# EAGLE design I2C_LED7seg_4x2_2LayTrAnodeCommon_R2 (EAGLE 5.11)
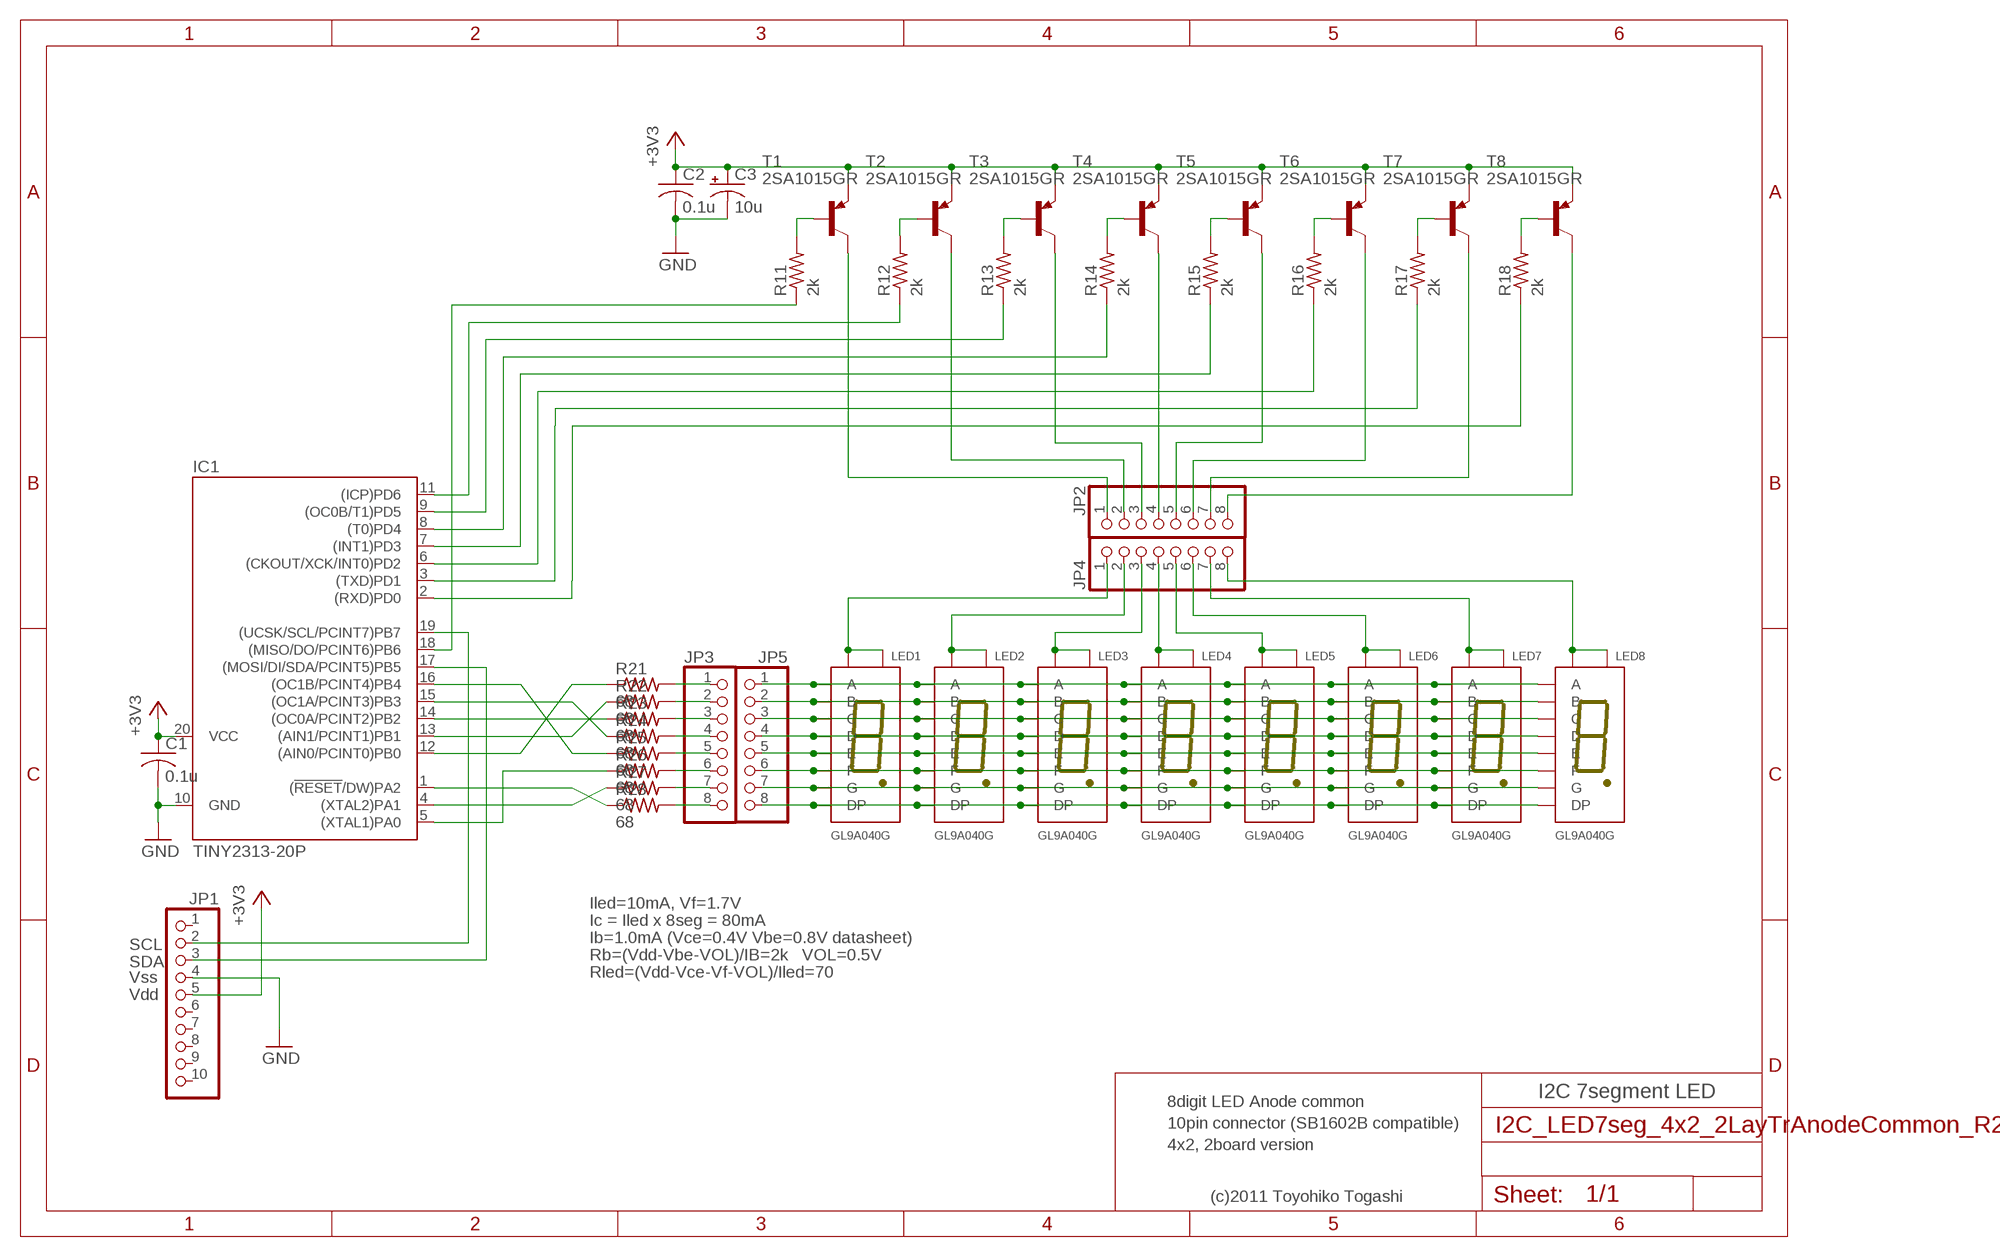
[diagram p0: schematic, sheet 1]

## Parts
C1  0.1u  C-US025-024X044  [C025-024X044]
C2  0.1u  C-US025-024X044  [C025-024X044]
C3  10u  CPOL-USE2.5-6  [E2,5-6]
IC1  TINY2313-20P  [DIL20]
JP1  PINHD-1X10  [1X10]
JP2  PINHD-1X8  [1X08]
JP3  PINHD-1X8  [1X08]
JP4  PINHD-1X8  [1X08]
JP5  PINHD-1X8  [1X08]
LED1  GL9A040G  [GL9A040G]
LED2  GL9A040G  [GL9A040G]
LED3  GL9A040G  [GL9A040G]
LED4  GL9A040G  [GL9A040G]
LED5  GL9A040G  [GL9A040G]
LED6  GL9A040G  [GL9A040G]
LED7  GL9A040G  [GL9A040G]
LED8  GL9A040G  [GL9A040G]
R11  2k  R-US_0207/10  [0207/10]
R12  2k  R-US_0204/2V  [0204V]
R13  2k  R-US_0204/2V  [0204V]
R14  2k  R-US_0204/2V  [0204V]
R15  2k  R-US_0204/7  [0204/7]
R16  2k  R-US_0204/7  [0204/7]
R17  2k  R-US_0204/2V  [0204V]
R18  2k  R-US_0204/5  [0204/5]
R21  68  R-US_0204/2V  [0204V]
R22  68  R-US_0204/2V  [0204V]
R23  68  R-US_0204/2V  [0204V]
R24  68  R-US_0204/2V  [0204V]
R25  68  R-US_0204/2V  [0204V]
R26  68  R-US_0204/2V  [0204V]
R27  68  R-US_0204/2V  [0204V]
R28  68  R-US_0204/2V  [0204V]
T1  2SA1015GR  2SC1815-PNP-TO92-BCE  [TO92-BCE]
T2  2SA1015GR  2SC1815-PNP-TO92-BCE  [TO92-BCE]
T3  2SA1015GR  2SC1815-PNP-TO92-BCE  [TO92-BCE]
T4  2SA1015GR  2SC1815-PNP-TO92-BCE  [TO92-BCE]
T5  2SA1015GR  2SC1815-PNP-TO92-BCE  [TO92-BCE]
T6  2SA1015GR  2SC1815-PNP-TO92-BCE  [TO92-BCE]
T7  2SA1015GR  2SC1815-PNP-TO92-BCE  [TO92-BCE]
T8  2SA1015GR  2SC1815-PNP-TO92-BCE  [TO92-BCE]

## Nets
+3V3: C1.1 C2.1 C3.+ IC1.20(VCC) JP1.5 T1.E T2.E T3.E T4.E T5.E T6.E T7.E T8.E
GND: C1.2 C2.2 C3.- IC1.10(GND) JP1.4
N$1: JP3.7 R27.2
N$2: JP3.8 R28.2
N$3: IC1.19((UCSK/SCL/PCINT7)PB7) JP1.2
N$4: IC1.17((MOSI/DI/SDA/PCINT5)PB5) JP1.3
N$5: JP3.1 R21.2
N$6: JP3.2 R22.2
N$7: JP3.3 R23.2
N$8: JP3.4 R24.2
N$9: JP3.5 R25.2
N$10: JP3.6 R26.2
N$11: JP2.8 T8.C
N$12: JP2.7 T7.C
N$13: R11.2 T1.B
N$14: IC1.5((XTAL1)PA0) R26.1
N$15: IC1.4((XTAL2)PA1) R27.1
N$16: IC1.1((!RESET!/DW)PA2) R28.1
N$17: IC1.12((AIN0/PCINT0)PB0) R21.1
N$18: JP4.1 LED1.P$1(CA1) LED1.P$6(CA6)
N$19: IC1.13((AIN1/PCINT1)PB1) R22.1
N$20: IC1.14((OC0A/PCINT2)PB2) R23.1
N$21: IC1.15((OC1A/PCINT3)PB3) R24.1
N$22: IC1.16((OC1B/PCINT4)PB4) R25.1
N$23: JP4.2 LED2.P$1(CA1) LED2.P$6(CA6)
N$24: JP4.3 LED3.P$1(CA1) LED3.P$6(CA6)
N$25: IC1.18((MISO/DO/PCINT6)PB6) R11.1
N$26: R18.2 T8.B
N$27: JP4.4 LED4.P$1(CA1) LED4.P$6(CA6)
N$28: IC1.2((RXD)PD0) R18.1
N$29: JP4.5 LED5.P$1(CA1) LED5.P$6(CA6)
N$30: JP4.6 LED6.P$1(CA1) LED6.P$6(CA6)
N$31: JP4.7 LED7.P$1(CA1) LED7.P$6(CA6)
N$32: JP4.8 LED8.P$1(CA1) LED8.P$6(CA6)
N$33: JP2.6 T6.C
N$34: JP2.5 T5.C
N$35: R12.2 T2.B
N$36: JP2.4 T4.C
N$37: JP2.3 T3.C
N$38: JP2.2 T2.C
N$39: JP2.1 T1.C
N$40: JP5.1 LED1.P$10(A) LED2.P$10(A) LED3.P$10(A) LED4.P$10(A) LED5.P$10(A) LED6.P$10(A) LED7.P$10(A) LED8.P$10(A)
N$41: JP5.2 LED1.P$9(B) LED2.P$9(B) LED3.P$9(B) LED4.P$9(B) LED5.P$9(B) LED6.P$9(B) LED7.P$9(B) LED8.P$9(B)
N$42: JP5.3 LED1.P$8(C) LED2.P$8(C) LED3.P$8(C) LED4.P$8(C) LED5.P$8(C) LED6.P$8(C) LED7.P$8(C) LED8.P$8(C)
N$43: JP5.4 LED1.P$5(D) LED2.P$5(D) LED3.P$5(D) LED4.P$5(D) LED5.P$5(D) LED6.P$5(D) LED7.P$5(D) LED8.P$5(D)
N$44: JP5.5 LED1.P$4(E) LED2.P$4(E) LED3.P$4(E) LED4.P$4(E) LED5.P$4(E) LED6.P$4(E) LED7.P$4(E) LED8.P$4(E)
N$45: JP5.6 LED1.P$2(F) LED2.P$2(F) LED3.P$2(F) LED4.P$2(F) LED5.P$2(F) LED6.P$2(F) LED7.P$2(F) LED8.P$2(F)
N$46: JP5.7 LED1.P$3(G) LED2.P$3(G) LED3.P$3(G) LED4.P$3(G) LED5.P$3(G) LED6.P$3(G) LED7.P$3(G) LED8.P$3(G)
N$47: JP5.8 LED1.P$7(DP) LED2.P$7(DP) LED3.P$7(DP) LED4.P$7(DP) LED5.P$7(DP) LED6.P$7(DP) LED7.P$7(DP) LED8.P$7(DP)
N$48: R13.2 T3.B
N$50: IC1.3((TXD)PD1) R17.1
N$53: IC1.7((INT1)PD3) R15.1
N$54: IC1.9((OC0B/T1)PD5) R13.1
N$60: R14.2 T4.B
N$72: R15.2 T5.B
N$84: R16.2 T6.B
N$96: R17.2 T7.B
N$98: IC1.11((ICP)PD6) R12.1
N$100: IC1.8((T0)PD4) R14.1
N$102: IC1.6((CKOUT/XCK/INT0)PD2) R16.1
Unconnected: JP1.1 JP1.6 JP1.7 JP1.8 JP1.9 JP1.10

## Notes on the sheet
- Iled=10mA, Vf=1.7V
- Ic = Iled x 8seg = 80mA
- Ib=1.0mA (Vce=0.4V Vbe=0.8V datasheet)
- SCL
- Rb=(Vdd-Vbe-VOL)/IB=2k   VOL=0.5V
- SDA
- Rled=(Vdd-Vce-Vf-VOL)/Iled=70
- Vss
- Vdd
- I2C 7segment LED
- 8digit LED Anode common
- 10pin connector (SB1602B compatible)
- 4x2, 2board version
- (c)2011 Toyohiko Togashi

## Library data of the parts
C1 C2 = rcl:C-US: CAPACITOR, American symbol
C3 = rcl:CPOL-US: POLARIZED CAPACITOR, American symbol
IC1 = TOG:TINY2313: 8-bit AVR Microcontroller with 2K Bytes Flash Source: http://www.atmel.com .. doc2543.pdf
JP1 = pinhead:PINHD-1X10: PIN HEADER
JP2-JP5 = pinhead:PINHD-1X8: PIN HEADER
LED1-LED8 = TOG:GL9A040G: 7 Segment LED
R11-R18 R21-R28 = rcl:R-US_: RESISTOR, American symbol
T1-T8 = transistor:*-PNP-: PNP Transistror

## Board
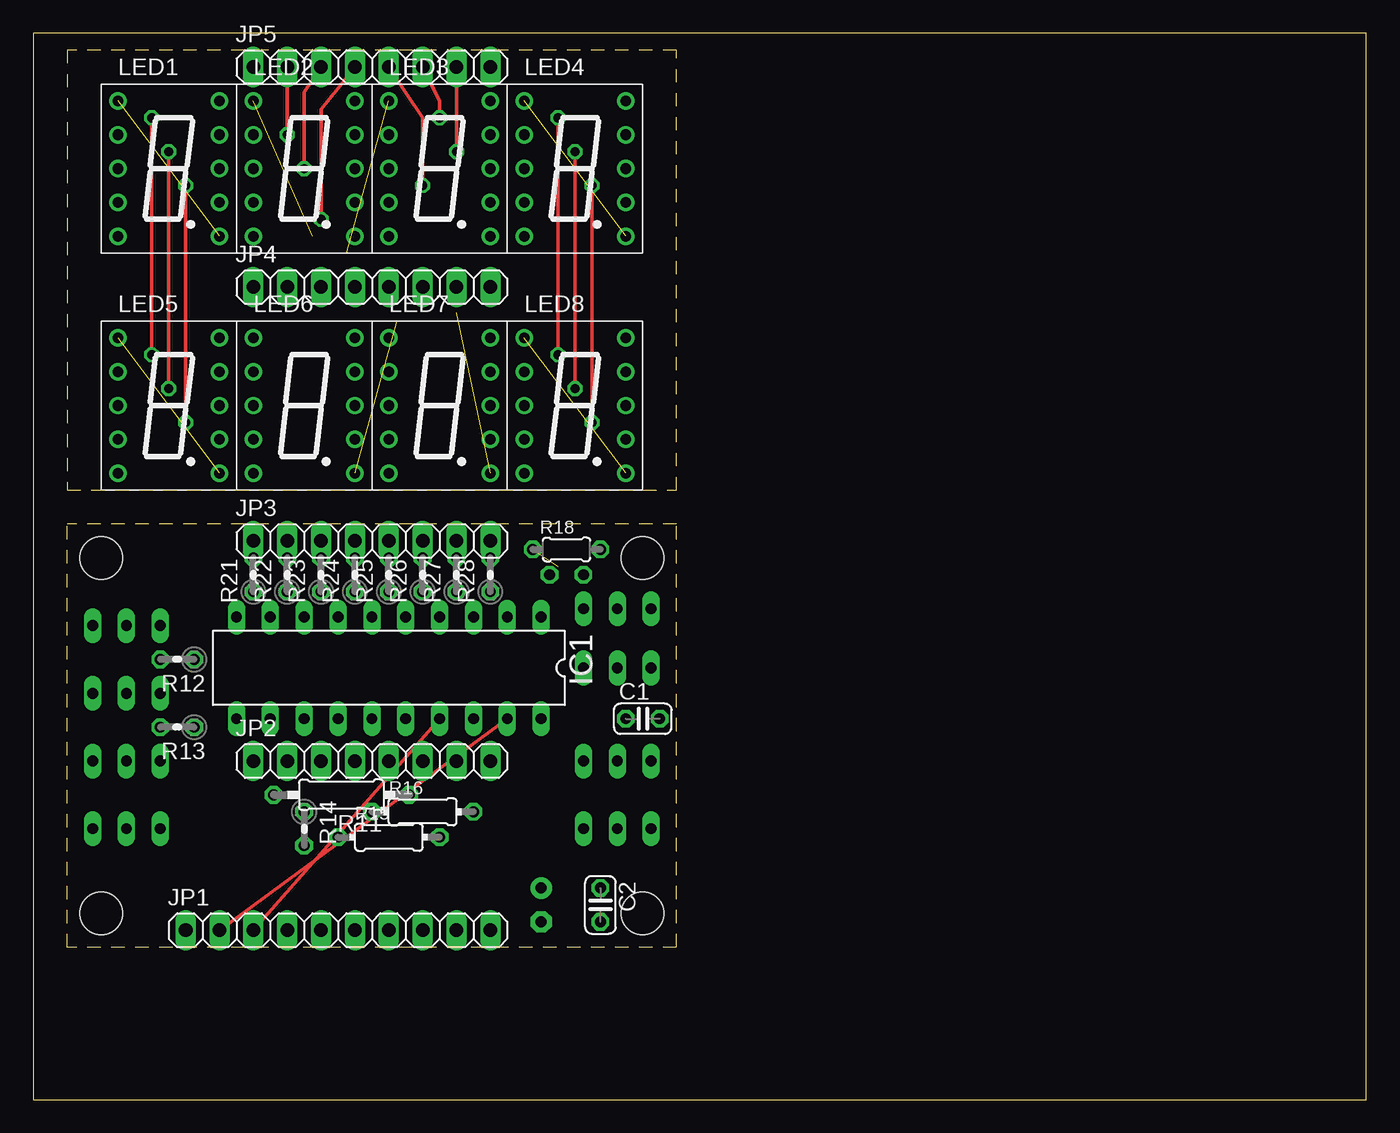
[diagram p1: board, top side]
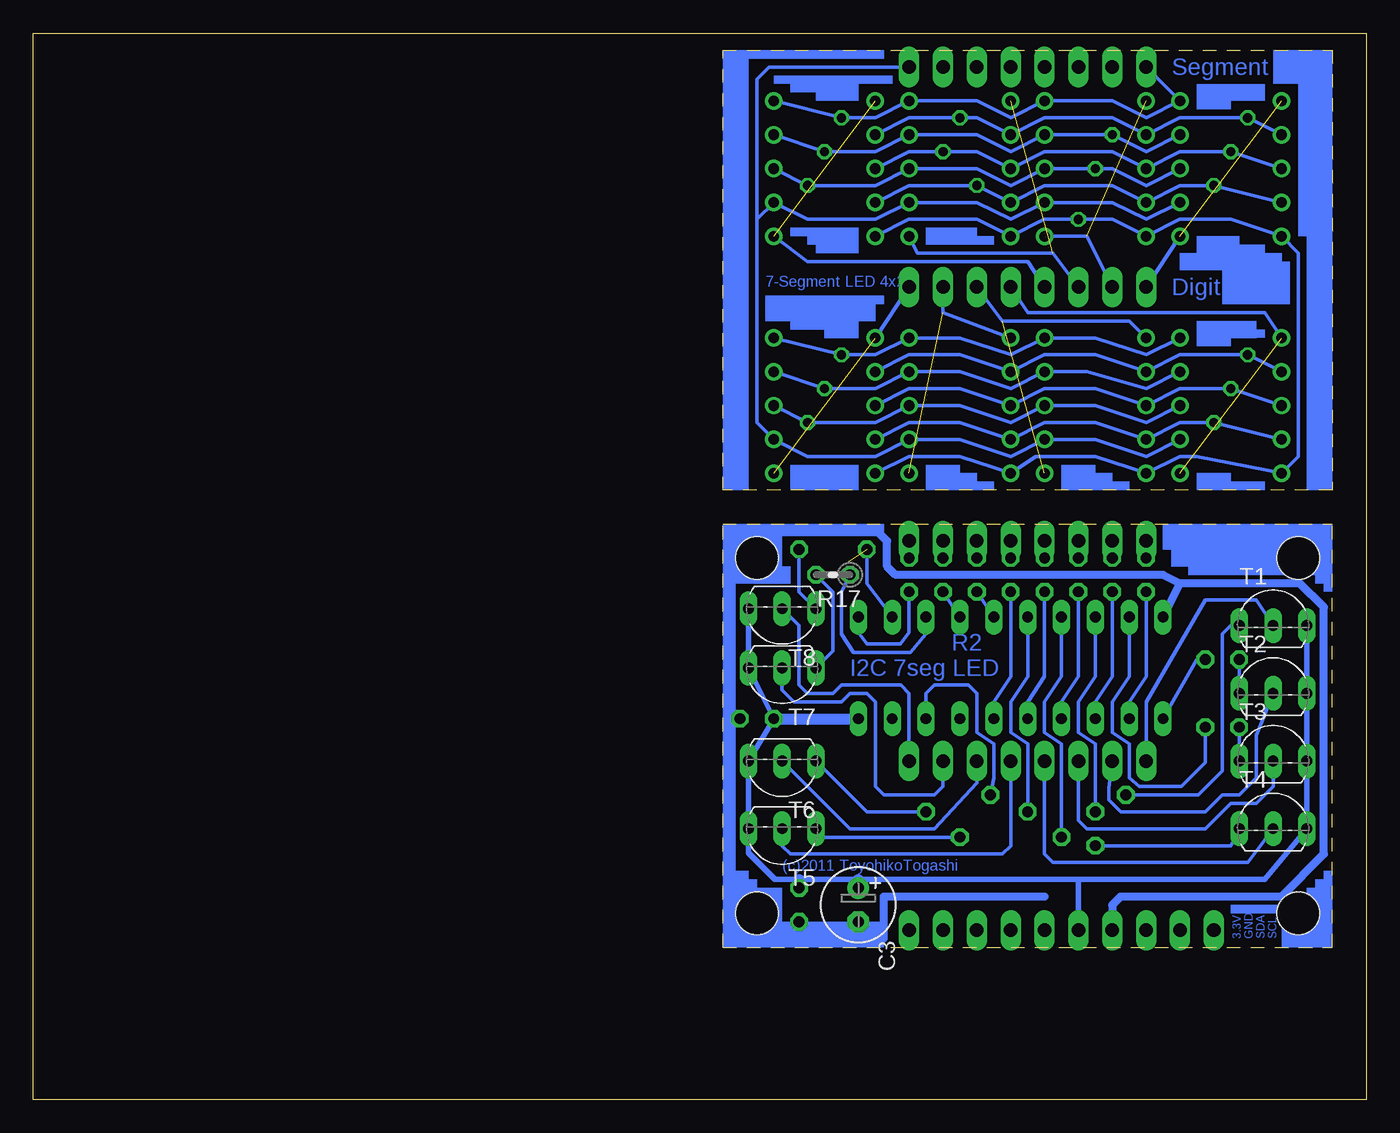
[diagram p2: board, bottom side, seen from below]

Size 100 x 80 mm. Coordinates in mm from the lower left corner, seen from the top.
Outline: 0,0 100,0 100,80 0,80 0,0
Outline: 2.54,78.74 2.54,45.72 48.26,45.72 48.26,78.74 2.54,78.74
Outline: 48.26,43.18 2.54,43.18 2.54,11.43 48.26,11.43 48.26,43.18
Copper layers (1*16): Top 0.035mm / dielectric 1.5mm / Bottom 0.035mm
Design rules "default": minimum track width 10mil, minimum drill 24mil, track to track 8mil, track to pad 8mil, pad to pad 8mil, via to via 8mil, smd to smd 8mil, copper to edge 40mil, drill to drill 8mil, minimum pad ring 10mil, minimum via ring 8mil, stop-mask expansion 4mil, vias tented up to drill 0mil, thermal gap 10mil
Holes 3.2 mm at 5.08,40.64 45.72,40.64 45.72,13.97 5.08,13.97

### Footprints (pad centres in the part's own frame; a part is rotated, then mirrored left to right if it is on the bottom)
C025-024X044 = drill 0.813 octagon: 1 -1.27,0; 2 1.27,0
E2,5-6 = drill 0.813 pad 1.6 round: + -1.27,0 | drill 0.813 pad 1.6 octagon: - 1.27,0
DIL20@1 = drill 0.813 long: 1 -11.43,-3.81; 2 -8.89,-3.81; 3 -6.35,-3.81; 4 -3.81,-3.81; 5 -1.27,-3.81; 6 1.27,-3.81; 7 3.81,-3.81; 8 6.35,-3.81; 9 8.89,-3.81; 10 11.43,-3.81; 11 11.43,3.81; 12 8.89,3.81; 13 6.35,3.81; 14 3.81,3.81; 15 1.27,3.81; 16 -1.27,3.81; 17 -3.81,3.81; 18 -6.35,3.81; 19 -8.89,3.81; 20 -11.43,3.81
1X10 = drill 1.016 long: 1 -11.43,0; 2 -8.89,0; 3 -6.35,0; 4 -3.81,0; 5 -1.27,0; 6 1.27,0; 7 3.81,0; 8 6.35,0; 9 8.89,0; 10 11.43,0
1X08 = drill 1.016 long: 1 -8.89,0; 2 -6.35,0; 3 -3.81,0; 4 -1.27,0; 5 1.27,0; 6 3.81,0; 7 6.35,0; 8 8.89,0
GL9A040G = drill 0.8 round: P$1 -3.81,5.08; P$2 -3.81,2.54; P$3 -3.81,0; P$4 -3.81,-2.54; P$5 -3.81,-5.08; P$6 3.81,-5.08; P$7 3.81,-2.54; P$8 3.81,0; P$9 3.81,2.54; P$10 3.81,5.08
0207/10 = drill 0.813 octagon: 1 -5.08,0; 2 5.08,0
0204V = drill 0.813 octagon: 1 -1.27,0; 2 1.27,0
0204/7 = drill 0.813 octagon: 1 -3.81,0; 2 3.81,0
0204/5 = drill 0.813 octagon: 1 -2.54,0; 2 2.54,0
TO92-BCE = drill 0.813 long: B -2.54,0; C 0,0; E 2.54,0

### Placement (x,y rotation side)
C1  45.72,28.57 0 top
C2  42.55,14.61 270 top
C3  38.1,14.61 270 bottom
IC1  TINY2313-20P  [DIL20@1]  26.67,32.38 180 top
JP1  22.86,12.7 0 top
JP2  25.4,25.4 0 top
JP3  25.4,41.91 0 top
JP4  25.4,60.96 0 top
JP5  25.4,77.47 0 top
LED1  10.16,69.85 0 top
LED2  20.32,69.85 0 top
LED3  30.48,69.85 0 top
LED4  40.64,69.85 0 top
LED5  10.16,52.07 0 top
LED6  20.32,52.07 0 top
LED7  30.48,52.07 0 top
LED8  40.64,52.07 0 top
R11  23.11,22.86 180 top
R12  10.79,33.02 180 top
R13  10.79,27.94 180 top
R14  20.32,20.32 270 top
R15  26.67,19.68 0 top
R16  29.21,21.59 0 top
R17  40.01,39.37 180 bottom
R18  40.01,41.27 0 top
R21  16.51,39.37 90 top
R22  19.05,39.37 90 top
R23  21.59,39.37 90 top
R24  24.13,39.37 90 top
R25  26.67,39.37 90 top
R26  29.21,39.37 90 top
R27  31.75,39.37 90 top
R28  34.29,39.37 90 top
T1  6.99,35.56 0 bottom
T2  6.99,30.48 0 bottom
T3  6.99,25.4 0 bottom
T4  6.99,20.32 0 bottom
T5  43.81,20.32 180 bottom
T6  43.81,25.4 180 bottom
T7  43.81,32.38 180 bottom
T8  43.81,36.83 180 bottom

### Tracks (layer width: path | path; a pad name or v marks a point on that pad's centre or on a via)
+3V3
  Bottom 0.406: T1.E T2.E T3.E T4.E 7.62,16.51 21.59,16.51 | T8.E T7.E C1.1 T6.E T5.E 46.35,18.52 44.35,16.51 42.55,16.51 38.1,16.51 21.59,16.51 | 21.59,16.51 JP1.5
  Bottom 0.813: C1.1 IC1.20 | 38.1,16.51 C3.+ | 42.55,16.51 C2.1
GND
  Bottom 0.61: JP1.4 19.05,14.61 18.41,15.24 6.35,15.24 3.17,18.41 3.17,36.94 4.97,38.73 13.97,38.73 | 13.97,38.73 15.24,39.37 35.31,39.37 35.94,40.01 35.94,41.91 36.58,42.55 46.73,42.55 47.62,41.65 47.62,28.57 47.62,12.06 42.55,12.06 38.1,12.06 36.2,12.06 36.2,15.24 24.13,15.24 | 13.97,38.73 IC1.10
  Bottom 0.813: 47.62,28.57 C1.2 | 38.1,12.06 C3.- | 42.55,12.06 C2.2
N$1
  Bottom 0.254: JP3.7 R27.2
N$2
  Bottom 0.254: R28.2 JP3.8
N$3
  Top 0.254: JP1.2 IC1.19
N$4
  Top 0.254: JP1.3 IC1.17
N$5
  Bottom 0.254: JP3.1 R21.2
N$6
  Bottom 0.254: JP3.2 R22.2
N$7
  Bottom 0.254: JP3.3 R23.2
N$8
  Bottom 0.254: JP3.4 R24.2
N$9
  Bottom 0.254: JP3.5 R25.2
N$10
  Bottom 0.254: JP3.6 R26.2
N$11
  Bottom 0.254: JP2.8 34.29,30.48 34.92,31.11 39.37,31.11 40.01,30.48 41.91,30.48 42.55,31.11 42.55,35.56 T8.C
N$12
  Bottom 0.254: T7.C 43.81,30.74 42.92,29.84 39.37,29.84 38.73,30.48 37.47,30.48 36.83,29.84 36.83,23.5 36.2,22.86 32.38,22.86 31.75,23.5 JP2.7
N$13
  Bottom 0.254: T1.B 10.16,35.56 10.79,34.92 10.79,24.66 12.59,22.86 R11.2
N$14
  Bottom 0.254: IC1.5 R26.1
N$15
  Bottom 0.254: IC1.4 R27.1
N$16
  Bottom 0.254: IC1.1 38.1,35.06 37.46,34.16 34.93,34.16 34.29,35.06 R28.1
N$17
  Bottom 0.254: R21.1 16.51,31.75 17.78,29.84 IC1.12
N$18  (1 unrouted)
  Bottom 0.254: JP4.1 LED1.P$6
N$19
  Bottom 0.254: R22.1 19.05,31.75 20.32,29.84 IC1.13
N$20
  Bottom 0.254: R23.1 21.59,31.75 22.86,29.84 IC1.14
N$21
  Bottom 0.254: R24.1 24.13,31.75 25.4,29.84 IC1.15
N$22
  Bottom 0.254: R25.1 26.67,31.75 27.94,29.84 IC1.16
N$23  (1 unrouted)
  Bottom 0.254: JP4.2 20.95,64.77 LED2.P$6
N$24  (1 unrouted)
  Bottom 0.254: JP4.3 23.5,63.5 33.66,63.5 LED3.P$6
N$25
  Bottom 0.254: R11.1 27.94,24.13 27.94,26.67 29.21,27.56 29.21,30.48 29.84,31.11 32.38,31.11 33.02,30.48 IC1.18
N$26
  Bottom 0.254: R18.2 42.55,38.1 T8.B
N$27  (1 unrouted)
  Bottom 0.254: JP4.4 25.4,62.87 41.91,62.87 LED4.P$6
N$28  (1 unrouted)
  Bottom 0.254: IC1.2 37.47,38.73 R18.1
N$29  (1 unrouted)
  Bottom 0.254: JP4.5 25.4,59.05 7.62,59.05 LED5.P$1
N$30  (1 unrouted)
  Bottom 0.254: JP4.6 27.3,58.42 17.78,58.42 LED6.P$1
N$31  (1 unrouted)
  Bottom 0.254: JP4.7 31.75,59.05 LED7.P$1
N$32  (1 unrouted)
  Bottom 0.254: LED8.P$1 JP4.8
N$33
  Bottom 0.254: T6.C 38.73,20.32 32.38,20.32 29.21,23.75 JP2.6
N$34
  Bottom 0.254: JP2.5 26.67,19.05 27.3,18.41 43.18,18.41 43.81,19.05 T5.C
N$35
  Bottom 0.254: R12.2 T2.B
N$36
  Bottom 0.254: T4.C 8.89,17.78 23.5,17.78 24.13,18.41 JP2.4
N$37
  Bottom 0.254: T3.C 6.99,23.5 8.26,22.23 10.16,22.23 12.06,20.32 20.95,20.32 21.59,20.95 JP2.3
N$38
  Bottom 0.254: T2.C 8.26,27.3 8.26,24.13 9.53,22.86 10.79,22.86 12.06,21.59 18.41,21.59 19.3,22.48 19.3,23.37 JP2.2
N$39
  Bottom 0.254: T1.C 8.26,37.47 12.06,37.47 16.51,29.84 JP2.1
N$40  (via drill 0.7)
  Top 0.254: v39.37,55.88 v39.37,73.66
  Bottom 0.254: LED5.P$10 16.51,55.88 20.32,57.15 LED6.P$10 26.67,55.88 30.48,57.15 LED7.P$10 36.83,55.88 v39.37,55.88 LED8.P$10 | LED4.P$10 v39.37,73.66 36.83,73.66 LED3.P$10 29.21,74.93 26.67,73.66 LED2.P$10 19.05,74.93 16.51,73.66 LED1.P$10 JP5.1
N$41  (via drill 0.7)
  Top 0.254: v40.64,53.34 v40.64,71.12 | v19.05,72.39 JP5.2
  Bottom 0.254: LED5.P$9 16.51,53.34 20.95,54.61 LED6.P$9 26.67,53.34 30.48,54.61 LED7.P$9 36.83,53.34 v40.64,53.34 LED8.P$9 | LED1.P$9 16.51,71.12 v19.05,72.39 LED2.P$9 26.67,71.12 29.21,72.39 LED3.P$9 36.83,71.12 v40.64,71.12 LED4.P$9
N$42  (via drill 0.7)
  Top 0.254: v41.91,50.8 v41.91,68.58 | JP5.3 20.32,75.56 v20.32,69.85
  Bottom 0.254: LED5.P$8 16.51,50.8 20.32,52.07 LED6.P$8 26.67,50.8 30.48,52.07 LED7.P$8 36.83,50.8 v41.91,50.8 LED8.P$8 | LED1.P$8 16.51,68.58 19.05,69.85 v20.32,69.85 LED2.P$8 26.67,68.58 29.21,69.85 LED3.P$8 36.83,68.58 v41.91,68.58 LED4.P$8
N$43  (via drill 0.7)
  Top 0.254: JP5.4 21.59,74.3 v21.59,66.04
  Bottom 0.254: LED8.P$5 34.29,48.26 30.48,48.26 LED7.P$5 24.77,48.26 20.32,48.26 LED6.P$5 13.97,48.26 12.7,48.26 LED5.P$5 5.08,48.26 5.08,63.5 LED1.P$5 10.16,66.04 13.97,66.04 LED2.P$5 19.05,66.04 v21.59,66.04 24.13,66.04 LED3.P$5 29.21,66.04 34.29,66.04 LED4.P$5
N$44  (via drill 0.7)
  Top 0.254: v11.43,50.8 v11.43,68.58 | JP5.5 29.21,73.66 v29.21,68.58
  Bottom 0.254: LED8.P$4 34.29,50.8 30.48,50.8 LED7.P$4 24.13,50.8 20.32,50.8 LED6.P$4 13.97,50.8 v11.43,50.8 LED5.P$4 | LED4.P$4 34.29,68.58 v29.21,68.58 LED3.P$4 24.13,68.58 19.05,68.58 LED2.P$4 13.97,68.58 v11.43,68.58 LED1.P$4
N$45  (via drill 0.7)
  Top 0.254: v8.89,55.88 v8.89,73.66 | JP5.6 30.48,74.93 v30.48,73.66
  Bottom 0.254: LED8.P$2 34.29,55.88 30.48,55.88 LED7.P$2 24.13,55.88 20.32,55.88 LED6.P$2 13.97,55.88 v8.89,55.88 LED5.P$2 | LED4.P$2 34.29,73.66 v30.48,73.66 29.21,73.66 LED3.P$2 24.13,73.66 19.05,73.66 LED2.P$2 13.97,73.66 v8.89,73.66 LED1.P$2
N$46  (via drill 0.7)
  Top 0.254: v10.16,53.34 v10.16,71.12 | v31.75,71.12 JP5.7
  Bottom 0.254: LED8.P$3 34.29,53.34 30.48,53.34 LED7.P$3 24.13,53.34 20.32,53.34 LED6.P$3 13.97,53.34 v10.16,53.34 LED5.P$3 | LED4.P$3 34.29,71.12 v31.75,71.12 29.21,71.12 LED3.P$3 24.13,71.12 19.05,71.12 LED2.P$3 13.97,71.12 v10.16,71.12 LED1.P$3
N$47
  Bottom 0.254: LED5.P$7 16.51,48.26 20.32,49.53 LED6.P$7 26.67,48.26 30.48,49.53 LED7.P$7 36.83,48.26 41.91,48.26 LED8.P$7 45.72,50.8 45.72,66.04 | LED1.P$7 16.51,66.04 19.05,67.31 LED2.P$7 26.67,66.04 29.21,67.31 LED3.P$7 36.83,66.04 41.91,66.04 LED4.P$7 45.72,66.04 | 45.72,66.04 45.72,76.57 44.82,77.47 JP5.8
N$48
  Bottom 0.254: T3.B R13.2
N$50
  Bottom 0.254: IC1.3 33.02,34.95 34.19,33.53 38.46,33.53 39.37,34.95 39.37,38.1 R17.1
N$53
  Bottom 0.254: R15.1 22.86,26.67 24.13,27.56 24.13,29.84 22.86,31.75 IC1.7
N$54
  Bottom 0.254: R13.1 12.06,25.29 13.86,23.5 17.02,23.5 17.78,24.13 17.78,26.67 19.05,27.56 19.05,29.84 17.78,31.75 IC1.9
N$60
  Bottom 0.254: T4.B 10.16,19.05 R14.2
N$72
  Bottom 0.254: R15.2 40.64,19.68 T5.B
N$84
  Bottom 0.254: R16.2 37.47,21.59 T6.B
N$96
  Bottom 0.254: T7.B 40.01,33.66 40.01,38.1 R17.2
N$98
  Bottom 0.254: R12.1 12.7,33.02 IC1.11
N$100
  Bottom 0.254: R14.1 20.32,26.67 21.59,27.56 21.59,29.84 20.32,31.75 IC1.8
N$102
  Bottom 0.254: R16.1 25.4,26.67 26.67,27.56 26.67,29.84 25.4,31.75 IC1.6
(copper drawn outside any net)
  shapes: Bottom area x69

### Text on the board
Bottom: Segment | 7-Segment LED 4x2 | Digit | R2 | I2C 7seg LED | (c)2011 ToyohikoTogashi | SCL | SDA | GND | 3.3V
